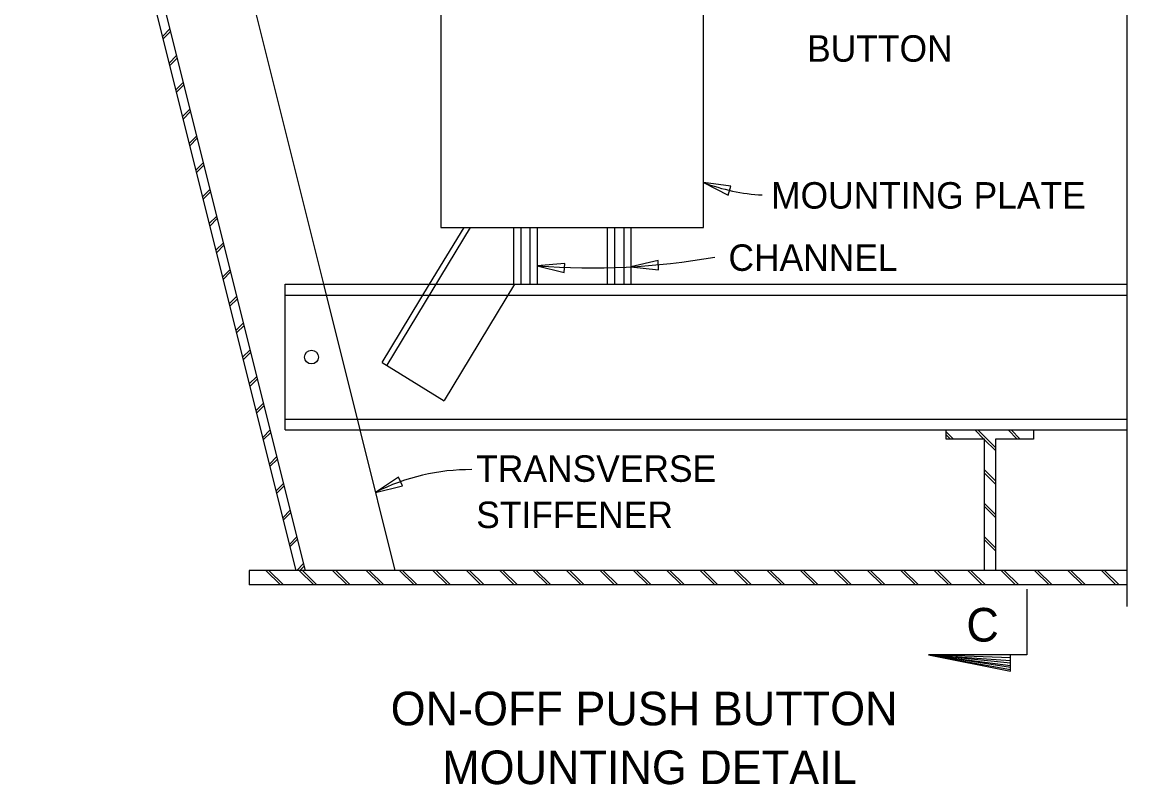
# Model space of a CAD drawing. Extents: x 927736.2 to 927809.6, y 636703.6 to 636757.7.
# Drawn here: x 927758.43 to 927774.19, y 636710.59 to 636721.33 of the extents above; entities that cross this region are included whole.
import ezdxf

# ---------------------------------------------------------------- set-up
doc = ezdxf.new("R2010")
doc.units = 0
for name, color, linetype in [('Default', 7, 'Continuous'), ('DimLines_dp', 7, 'Continuous'), ('Miscellaneous1', 7, 'Continuous'), ('Miscellaneous3', 7, 'Continuous')]:
    doc.layers.add(name, color=color, linetype=linetype)

msp = doc.modelspace()

# ---------------------------------------------------------------- linework, layer by layer
at = {"layer": 'DimLines_dp'}
for p, q in [((927772.357, 636712.378), (927771.201, 636712.421)), ((927771.201, 636712.421), (927772.357, 636712.341)), ((927772.357, 636712.307), (927771.201, 636712.421)), ((927771.201, 636712.421), (927772.357, 636712.273)), ((927772.357, 636712.242), (927771.201, 636712.421)), ((927771.201, 636712.421), (927772.357, 636712.218))]:
    msp.add_line(p, q, dxfattribs=at)
for points in [[(927774, 636713.104), (927774, 636722.378), (927773.809, 636722.378), (927774, 636722.461), (927774.191, 636722.544), (927774, 636722.544), (927774, 636731.999)], [(927772.589, 636713.346), (927772.589, 636712.421), (927771.201, 636712.421), (927772.357, 636712.19), (927772.357, 636712.421)]]:
    msp.add_lwpolyline(points, dxfattribs=at)
for points in [[(927768.032, 636719.079), (927768.38, 636718.901), (927768.419, 636719.026)], [(927767.01, 636717.89), (927767.398, 636717.846), (927767.391, 636717.977)], [(927765.688, 636717.904), (927766.067, 636717.809), (927766.077, 636717.939)], [(927763.409, 636714.711), (927763.788, 636714.806), (927763.736, 636714.926)]]:
    msp.add_lwpolyline(points, close=True, dxfattribs=at)
for centre, radius, start, end in [((927768.996, 636721.566), 2.667, 248.8193, 267.0903), ((927766.454, 636727.853), 9.978, 265.6012, 280.0186)]:
    msp.add_arc(centre, radius, start, end, dxfattribs=at)
msp.add_ellipse((927764.747, 636711.794), major_axis=(-0.021, -3.238), ratio=0.953713, start_param=3.141601, end_param=3.59647, dxfattribs=at)
at = {"layer": 'Miscellaneous1'}
for p, q in [((927765.354, 636718.446), (927765.354, 636717.646)), ((927765.457, 636718.446), (927765.457, 636717.646)), ((927765.586, 636718.446), (927765.586, 636717.646)), ((927765.688, 636718.446), (927765.688, 636717.646)), ((927766.676, 636718.446), (927766.676, 636717.646)), ((927766.778, 636718.446), (927766.778, 636717.646)), ((927766.907, 636718.446), (927766.907, 636717.646)), ((927767.01, 636718.446), (927767.01, 636717.646))]:
    msp.add_line(p, q, dxfattribs=at)
at = {"layer": 'Miscellaneous3'}
for p, q in [((927758.434, 636729.029), (927762.288, 636713.612)), ((927758.566, 636729.029), (927762.42, 636713.612)), ((927760.241, 636727.384), (927762.676, 636717.646)), ((927760.407, 636721.137), (927760.513, 636721.243)), ((927760.416, 636721.102), (927760.522, 636721.208)), ((927760.501, 636720.76), (927760.607, 636720.866)), ((927760.51, 636720.725), (927760.616, 636720.831)), ((927760.595, 636720.383), (927760.701, 636720.489)), ((927760.604, 636720.349), (927760.71, 636720.454)), ((927760.689, 636720.007), (927760.795, 636720.113)), ((927760.698, 636719.972), (927760.804, 636720.078)), ((927760.784, 636719.63), (927760.89, 636719.736)), ((927760.792, 636719.595), (927760.898, 636719.701)), ((927760.878, 636719.253), (927760.984, 636719.359)), ((927760.886, 636719.218), (927760.992, 636719.324)), ((927760.972, 636718.876), (927761.078, 636718.982)), ((927760.981, 636718.842), (927761.087, 636718.948)), ((927761.066, 636718.5), (927761.172, 636718.606)), ((927761.075, 636718.465), (927761.181, 636718.571)), ((927763.572, 636716.504), (927764.747, 636718.446)), ((927764.173, 636717.646), (927764.657, 636718.446)), ((927761.16, 636718.123), (927761.266, 636718.229)), ((927761.169, 636718.088), (927761.275, 636718.194)), ((927761.254, 636717.746), (927761.36, 636717.852)), ((927761.263, 636717.711), (927761.369, 636717.817)), ((927762.138, 636717.646), (927774, 636717.646)), ((927762.138, 636715.591), (927762.138, 636717.646)), ((927762.675, 636717.646), (927763.189, 636715.591)), ((927763.506, 636716.544), (927764.173, 636717.646)), ((927764.383, 636716.007), (927765.374, 636717.646)), ((927761.349, 636717.369), (927761.455, 636717.475)), ((927761.357, 636717.335), (927761.463, 636717.441)), ((927762.138, 636717.492), (927774, 636717.492)), ((927761.443, 636716.993), (927761.549, 636717.099)), ((927761.452, 636716.958), (927761.558, 636717.064)), ((927761.537, 636716.616), (927761.643, 636716.722)), ((927761.546, 636716.581), (927761.652, 636716.687)), ((927763.506, 636716.544), (927764.379, 636716.002)), ((927761.631, 636716.239), (927761.737, 636716.345)), ((927761.64, 636716.204), (927761.746, 636716.31)), ((927761.725, 636715.862), (927761.831, 636715.968)), ((927761.734, 636715.828), (927761.84, 636715.934)), ((927762.138, 636715.745), (927774, 636715.745)), ((927761.82, 636715.486), (927761.926, 636715.592)), ((927761.828, 636715.451), (927761.934, 636715.557)), ((927762.138, 636715.591), (927774, 636715.591)), ((927763.189, 636715.591), (927763.684, 636713.612)), ((927771.555, 636715.462), (927771.45, 636715.567)), ((927771.511, 636715.462), (927771.45, 636715.523)), ((927771.982, 636715.462), (927771.853, 636715.591)), ((927772.144, 636715.344), (927771.897, 636715.591)), ((927772.144, 636715.3), (927771.99, 636715.454)), ((927772.453, 636715.462), (927772.324, 636715.591)), ((927772.496, 636715.462), (927772.368, 636715.591)), ((927761.914, 636715.109), (927762.02, 636715.215)), ((927761.923, 636715.074), (927762.028, 636715.18)), ((927772.144, 636714.873), (927771.99, 636715.027)), ((927772.144, 636714.829), (927771.99, 636714.983)), ((927762.008, 636714.732), (927762.114, 636714.838)), ((927762.017, 636714.697), (927762.123, 636714.803)), ((927772.144, 636714.402), (927771.99, 636714.556)), ((927772.144, 636714.358), (927771.99, 636714.512)), ((927762.102, 636714.355), (927762.208, 636714.461)), ((927762.111, 636714.321), (927762.217, 636714.427)), ((927762.196, 636713.979), (927762.302, 636714.085)), ((927762.205, 636713.944), (927762.311, 636714.05)), ((927772.144, 636713.931), (927771.99, 636714.085)), ((927772.144, 636713.887), (927771.99, 636714.041)), ((927763.433, 636713.612), (927761.631, 636713.612)), ((927761.631, 636713.612), (927761.631, 636713.407)), ((927761.631, 636713.612), (927761.631, 636713.407)), ((927762.07, 636713.407), (927761.864, 636713.612)), ((927762.113, 636713.407), (927761.908, 636713.612)), ((927762.301, 636713.612), (927762.397, 636713.708)), ((927762.541, 636713.407), (927762.335, 636713.612)), ((927762.344, 636713.612), (927762.405, 636713.673)), ((927762.584, 636713.407), (927762.379, 636713.612)), ((927763.012, 636713.407), (927762.806, 636713.612)), ((927763.055, 636713.407), (927762.85, 636713.612)), ((927763.483, 636713.407), (927763.277, 636713.612)), ((927763.526, 636713.407), (927763.321, 636713.612)), ((927772.067, 636713.612), (927763.434, 636713.612)), ((927763.953, 636713.407), (927763.748, 636713.612)), ((927763.997, 636713.407), (927763.792, 636713.612)), ((927764.424, 636713.407), (927764.219, 636713.612)), ((927764.468, 636713.407), (927764.263, 636713.612)), ((927764.895, 636713.407), (927764.69, 636713.612)), ((927764.939, 636713.407), (927764.734, 636713.612)), ((927765.366, 636713.407), (927765.161, 636713.612)), ((927765.41, 636713.407), (927765.204, 636713.612)), ((927765.837, 636713.407), (927765.632, 636713.612)), ((927765.881, 636713.407), (927765.675, 636713.612)), ((927766.308, 636713.407), (927766.103, 636713.612)), ((927766.352, 636713.407), (927766.146, 636713.612)), ((927766.779, 636713.407), (927766.574, 636713.612)), ((927766.823, 636713.407), (927766.617, 636713.612)), ((927767.25, 636713.407), (927767.045, 636713.612)), ((927767.294, 636713.407), (927767.088, 636713.612)), ((927767.721, 636713.407), (927767.516, 636713.612)), ((927767.765, 636713.407), (927767.559, 636713.612)), ((927768.192, 636713.407), (927767.986, 636713.612)), ((927768.235, 636713.407), (927768.03, 636713.612)), ((927768.663, 636713.407), (927768.457, 636713.612)), ((927768.706, 636713.407), (927768.501, 636713.612)), ((927769.134, 636713.407), (927768.928, 636713.612)), ((927769.177, 636713.407), (927768.972, 636713.612)), ((927769.605, 636713.407), (927769.399, 636713.612)), ((927769.648, 636713.407), (927769.443, 636713.612)), ((927770.076, 636713.407), (927769.87, 636713.612)), ((927770.119, 636713.407), (927769.914, 636713.612)), ((927770.547, 636713.407), (927770.341, 636713.612)), ((927770.59, 636713.407), (927770.385, 636713.612)), ((927771.017, 636713.407), (927770.812, 636713.612)), ((927771.061, 636713.407), (927770.856, 636713.612)), ((927771.488, 636713.407), (927771.283, 636713.612)), ((927771.532, 636713.407), (927771.327, 636713.612)), ((927771.959, 636713.407), (927771.754, 636713.612)), ((927772.003, 636713.407), (927771.798, 636713.612)), ((927771.992, 636713.612), (927771.99, 636713.614)), ((927774, 636713.612), (927772.067, 636713.612)), ((927772.43, 636713.407), (927772.225, 636713.612)), ((927772.474, 636713.407), (927772.268, 636713.612)), ((927772.901, 636713.407), (927772.696, 636713.612)), ((927772.945, 636713.407), (927772.739, 636713.612)), ((927773.372, 636713.407), (927773.167, 636713.612)), ((927773.416, 636713.407), (927773.21, 636713.612)), ((927773.843, 636713.407), (927773.638, 636713.612)), ((927773.887, 636713.407), (927773.681, 636713.612)), ((927761.642, 636713.407), (927761.631, 636713.418)), ((927774, 636713.407), (927761.631, 636713.407))]:
    msp.add_line(p, q, dxfattribs=at)
for points in [[(927768.032, 636718.446), (927768.032, 636718.446), (927768.032, 636726.463), (927766.275, 636726.463)], [(927764.332, 636723.646), (927764.332, 636718.446), (927768.032, 636718.446)]]:
    msp.add_lwpolyline(points, dxfattribs=at)
msp.add_lwpolyline([(927771.99, 636713.612), (927771.99, 636715.462), (927771.45, 636715.462), (927771.45, 636715.591), (927772.683, 636715.591), (927772.683, 636715.462), (927772.144, 636715.462), (927772.144, 636713.612)], close=True, dxfattribs=at)
msp.add_circle((927762.508, 636716.618), 0.0964, dxfattribs=at)

# ---------------------------------------------------------------- texts
at = {"layer": 'Default'}
for s, p in [('ON-OFF PUSH BUTTON', (927763.624, 636711.429)), ('MOUNTING DETAIL', (927764.349, 636710.6))]:
    msp.add_text(s, height=0.4736, dxfattribs=at).set_placement(p)
at = {"layer": 'DimLines_dp'}
for s, height, p in [('BUTTON', 0.373, (927769.492, 636720.78)), ('MOUNTING PLATE', 0.37296, (927768.984, 636718.71)), ('CHANNEL', 0.373, (927768.383, 636717.833)), ('TRANSVERSE', 0.373, (927764.829, 636714.86)), ('STIFFENER', 0.373, (927764.829, 636714.209)), ('C', 0.474, (927771.736, 636712.609))]:
    msp.add_text(s, height=height, dxfattribs=at).set_placement(p)

doc.saveas('drawing.dxf')
